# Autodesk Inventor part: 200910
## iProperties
Created: 2007-11
Part Number: 200910
Material: Acetal Resin, White
Document SubType Name: Modeling
Designer: JJ
Density: 1.42 g/cm^3
Mass: 5.8341 g
Surface Area: 32.5628 cm^2
Volume: 4.10852 cm^3
Description: WORM GEAR
CustomPartVersion: 1
Component Category: Lower Component
Author: JJ
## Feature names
1. Base Body [Extrusion]
2. Chamfer1
3. Chamfer2
4. Tooth
5. Tooth Pattern [Circular Pattern]
6. Left Tooth
7. Left Tooth Pattern [Circular Pattern]
8. Extrusion2
9. Chamfer3
10. Revolution1
11. Mirror1
12. Extrusion3
13. Fillet1
